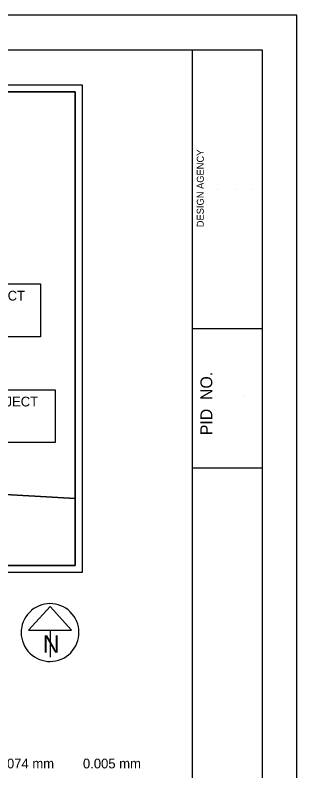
# Model space of a CAD drawing. Extents: x 0 to 34, y 0 to 22.
# Drawn here: x 29.95 to 34, y 11.15 to 22 of the extents above; entities that cross this region are included whole.
import ezdxf

# ---------------------------------------------------------------- set-up
doc = ezdxf.new("R2010")
doc.units = 0
for name, color, linetype in [('GM_X_Adjacent_County', 7, 'Continuous'), ('SH_Border', 7, 'Continuous'), ('SH_Cut_Line', 7, 'Continuous'), ('SH_Data', 7, 'Continuous'), ('SH_Text', 7, 'Continuous')]:
    doc.layers.add(name, color=color, linetype=linetype)

msp = doc.modelspace()

# ---------------------------------------------------------------- linework, layer by layer
at = {"layer": 'GM_X_Adjacent_County'}
for points in [[(29.025, 20.9), (28.952, 20.455), (28.875, 20.061), (28.567, 18.366), (28.415, 17.556), (28.218, 16.655), (28.184, 16.461), (28.004, 15.594), (28, 15.573), (27.946, 15.267), (28.327, 15.217), (28.534, 15.206), (29.545, 15.136), (29.721, 15.125), (30.239, 15.094), (30.817, 15.059)], [(30.817, 15.059), (30.817, 20.9), (29.025, 20.9)], [(30.817, 15.059), (30.239, 15.094), (29.721, 15.125), (29.545, 15.136), (28.534, 15.206), (28.327, 15.217), (27.946, 15.267), (27.623, 15.187), (26.446, 14.932), (26.408, 14.926), (24.826, 14.648), (24.698, 14.628), (24.017, 14.521)], [(24.017, 14.521), (24.017, 14.1), (30.817, 14.1), (30.817, 15.059)]]:
    msp.add_lwpolyline(points, dxfattribs=at)
at = {"layer": 'SH_Border'}
for p, q in [((32.5, 0.5), (32.5, 21.5)), ((32.5, 17.5), (33.5, 17.5)), ((32.5, 15.5), (33.5, 15.5)), ((32.5, 15.5), (33.5, 15.5))]:
    msp.add_line(p, q, dxfattribs=at)
msp.add_lwpolyline([(2, 21.5), (33.5, 21.5), (33.5, 0.5), (2, 0.5)], close=True, dxfattribs=at)
at = {"layer": 'SH_Cut_Line'}
msp.add_lwpolyline([(0, 0), (34, 0), (34, 22), (0, 22)], close=True, dxfattribs=at)
at = {"layer": 'SH_Data'}
for p, q in [((32.863, 19.5), (32.863, 19.5)), ((33.113, 19.5), (33.113, 19.5)), ((33.363, 19.5), (33.363, 19.5)), ((33.25, 16.537), (33.25, 16.537)), ((30.456, 13.511), (30.148, 13.17)), ((30.764, 13.17), (30.456, 13.511)), ((30.148, 13.17), (30.764, 13.17)), ((30.456, 13.17), (30.456, 12.783))]:
    msp.add_line(p, q, dxfattribs=at)
for points in [[(23.917, 21), (30.917, 21), (30.917, 14), (23.917, 14)], [(24.017, 20.9), (30.817, 20.9), (30.817, 14.1), (24.017, 14.1)], [(28.676, 18.143), (30.32, 18.143), (30.32, 17.383), (28.676, 17.383)], [(28.676, 16.623), (30.528, 16.623), (30.528, 15.863), (28.676, 15.863)]]:
    msp.add_lwpolyline(points, close=True, dxfattribs=at)
msp.add_arc((30.456, 13.137), 0.415, 129.7798, 129.7633, dxfattribs=at)

# ---------------------------------------------------------------- texts
for s, height, p in [('DESIGN AGENCY', 0.1, (32.663, 18.955)), ('PID  NO.', 0.17, (32.785, 15.97))]:
    msp.add_text(s, height=height, rotation=90, dxfattribs=at).set_placement(p)
msp.add_text('N', height=0.25, dxfattribs=at).set_placement((30.352, 12.846))
at = {"layer": 'SH_Text'}
for s, p in [('END PROJECT ', (28.776, 17.903)), ('BEGIN PROJECT ', (28.776, 16.383)), ('0.074 mm', (29.681, 11.187)), ('0.005 mm', (30.928, 11.187))]:
    msp.add_text(s, height=0.14, dxfattribs=at).set_placement(p)

doc.saveas('drawing.dxf')
